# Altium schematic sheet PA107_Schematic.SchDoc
size A3; SheetNumber: 1; SheetTotal: 1
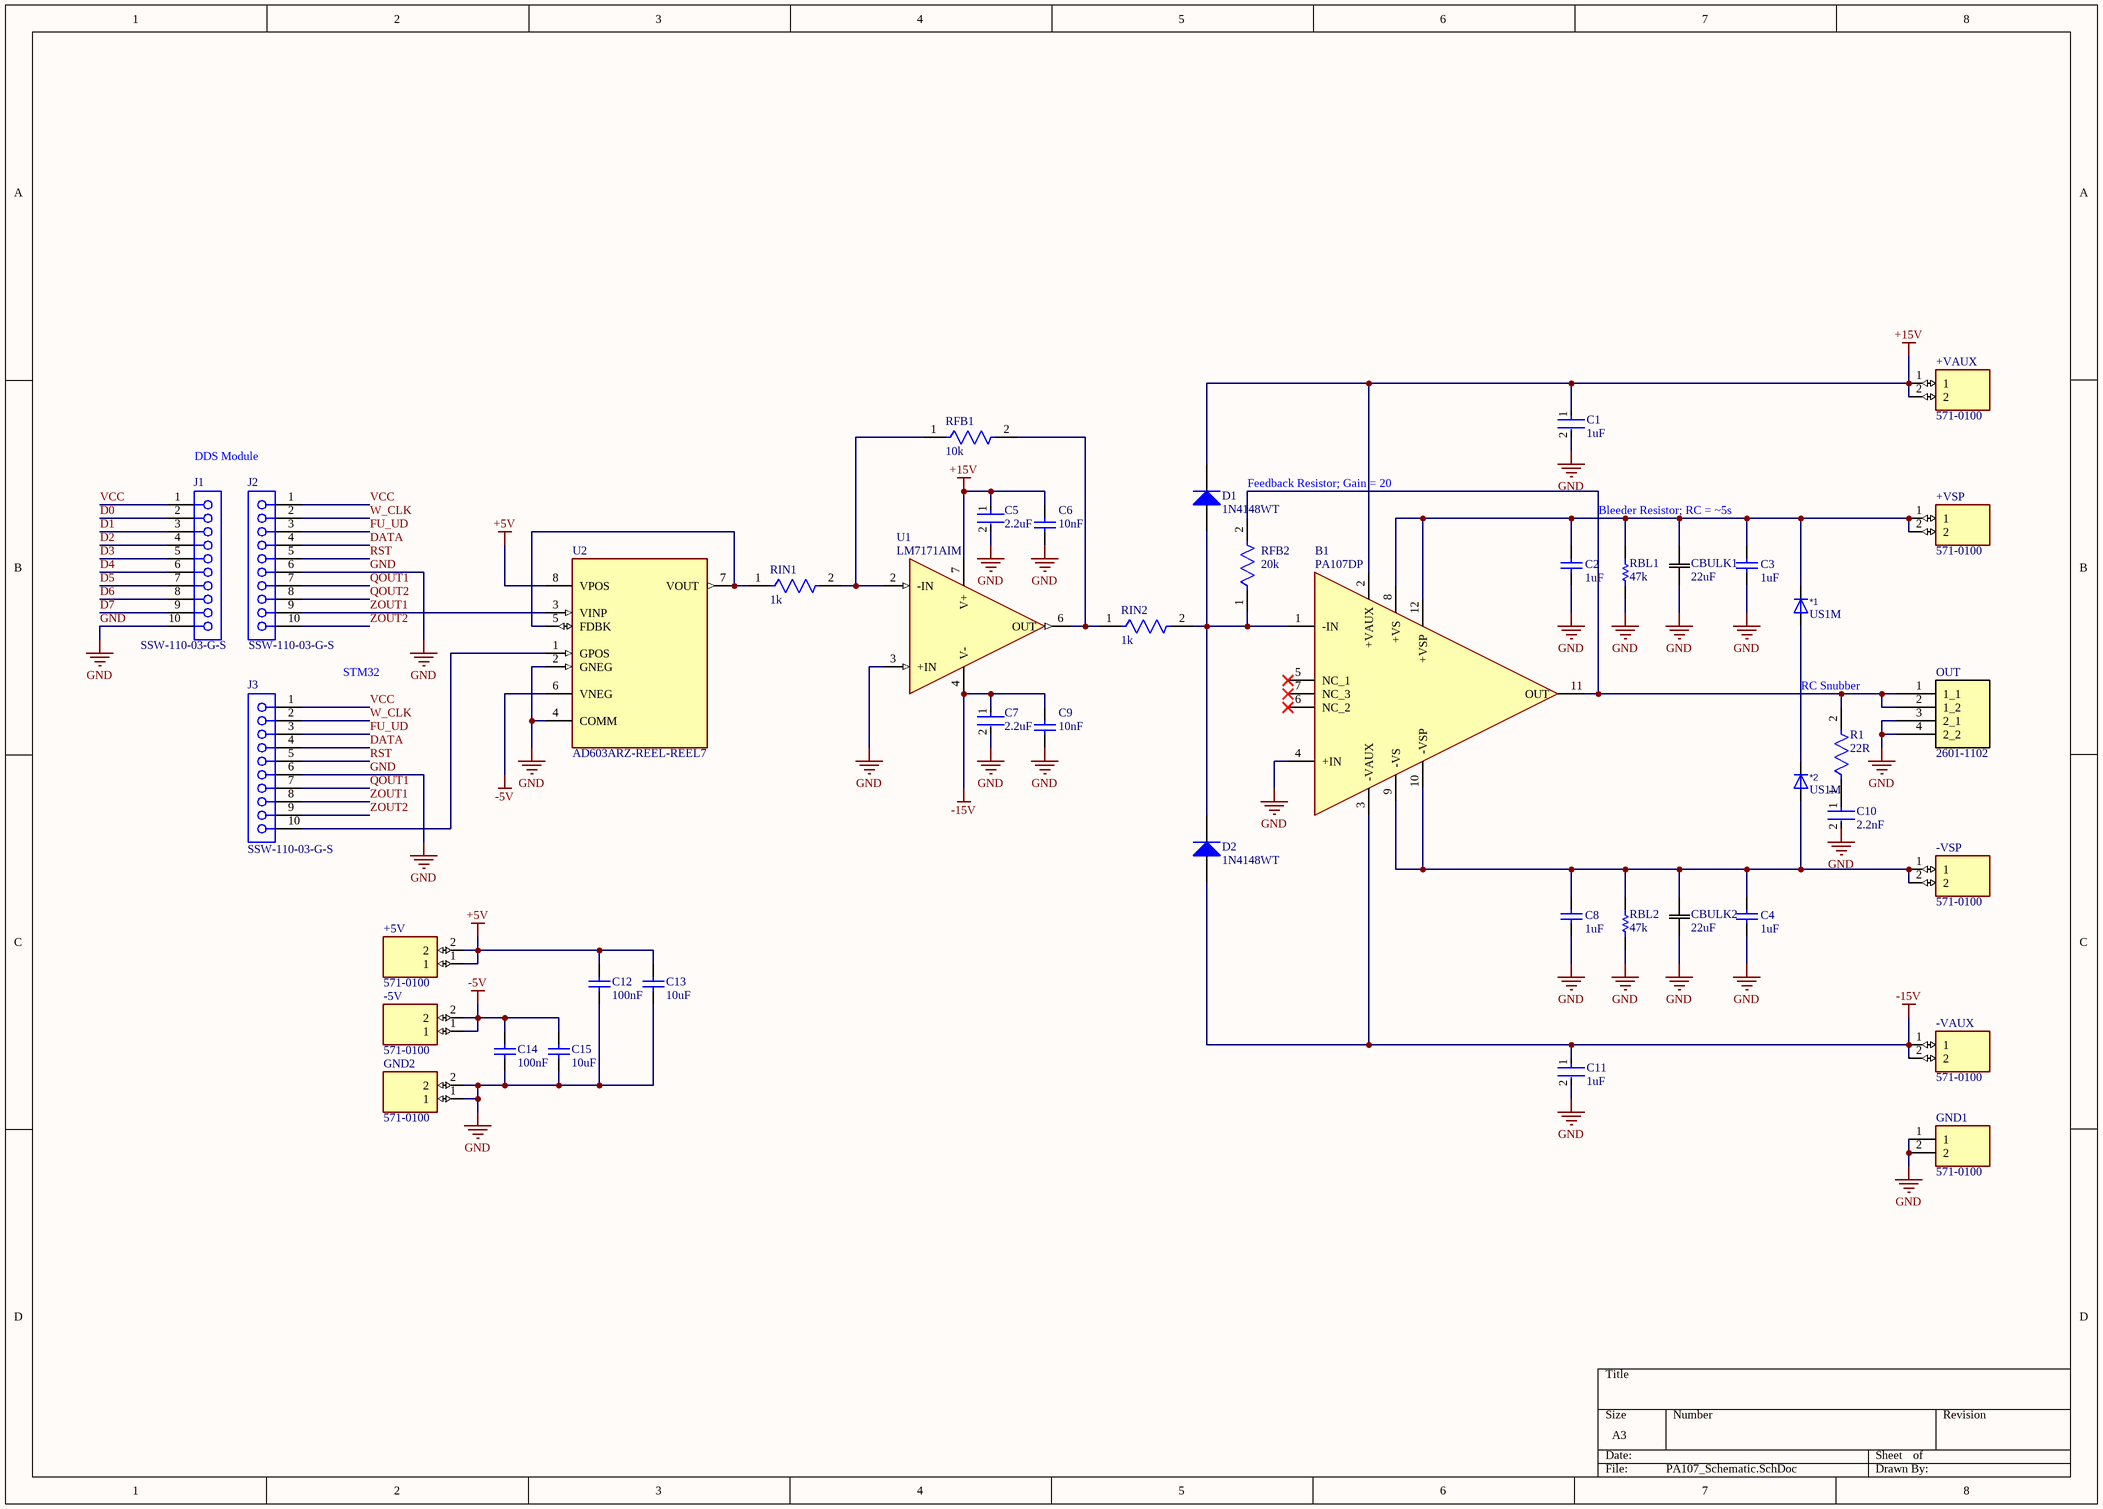
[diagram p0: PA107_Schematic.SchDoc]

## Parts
*1  US1M  [DO-214AC_SMA]
*2  US1M  [DO-214AC_SMA]
+5V  571-0100  [571-0100]
+VAUX  571-0100  [571-0100]
+VSP  571-0100  [571-0100]
-5V  571-0100  [571-0100]
-VAUX  571-0100  [571-0100]
-VSP  571-0100  [571-0100]
B1  PA107DP  [PA107DP]
C1  1uF  [FP-CC0805-0_85-MFG]
C2  1uF  [CAPC4532X279N]
C3  1uF  [CAPC4532X279N]
C4  1uF  [CAPC4532X279N]
C5  2.2uF  [FP-CC0805-0_85-MFG]
C6  10nF  [CAPC2013X145X48LL20T23]
C7  2.2uF  [FP-CC0805-0_85-MFG]
C8  1uF  [CAPC4532X279N]
C9  10nF  [CAPC2013X145X48LL20T23]
C10  2.2nF  [FP-HV1812-IPC_A]
C11  1uF  [FP-CC0805-0_85-MFG]
C12  100nF  [CAPC2013X145X48LL20T23]
C13  10uF  [CAPC2013X140X50ML20T25]
C14  100nF  [CAPC2013X145X48LL20T23]
C15  10uF  [CAPC2013X140X50ML20T25]
CBULK1  22uF  [CAP_BX_10x16_RUB]
CBULK2  22uF  [CAP_BX_10x16_RUB]
D1  1N4148WT  [FAIR-SOD-523F-2_V]
D2  1N4148WT  [FAIR-SOD-523F-2_V]
GND1  571-0100  [5710100]
GND2  571-0100  [571-0100]
J1  SSW-110-03-G-S  [SMTC-SSW-110-03-X-S]
J2  SSW-110-03-G-S  [SMTC-SSW-110-03-X-S]
J3  SSW-110-03-G-S  [SMTC-SSW-110-03-X-S]
OUT  2601-1102  [CONN2_2601-1102_WAG]
R1  22R  [FP-CRGP2512-IPC_C]
RBL1  47k  [RESC1210(3225)_L]
RBL2  47k  [RESC1210(3225)_L]
RFB1  10k  [FP-SR0805-MFG]
RFB2  20k  [FP-CRCW0805-HPe3-IPC_A]
RIN1  1k  [FP-CRCW0805-HPe3-IPC_B]
RIN2  1k  [FP-CRCW0805-HPe3-IPC_B]
U1  LM7171AIM  [SOIC127P599X175-8N]
U2  AD603ARZ-REEL-REEL7  [SOIC127P600X175-8N]

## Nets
+5V: +5V.1 +5V.2 C12.2 C13.2 U2.8(VPOS)
+15V: +VAUX.1 +VAUX.2 B1.2(+VAUX) C1.1 C5.1 C6.2 D1.1(K) U1.7(V+)
-5V: -5V.1 -5V.2 C14.2 C15.2 U2.6(VNEG)
-15V: -VAUX.1 -VAUX.2 B1.3(-VAUX) C7.1 C9.2 C11.1 D2.2(A) U1.4(V-)
GND: B1.4(+IN) C1.2 C2.1 C3.1 C4.1 C5.2 C6.1 C7.2 C8.1 C9.1 C10.2 C11.2 C12.1 C13.1 C14.1 C15.1 CBULK1.1 CBULK2.1 GND1.1 GND1.2 GND2.1 GND2.2 J1.10 J2.6 J3.6 OUT.3(2_1) OUT.4(2_2) RBL1.1 RBL2.1 U1.3(+IN) U2.2(GNEG) U2.4(COMM)
D0: J1.2
D1: J1.3
D2: J1.4
D3: J1.5
D4: J1.6
D5: J1.7
D6: J1.8
D7: J1.9
DATA: J2.4 J3.4
FU_UD: J2.3 J3.3
QOUT1: J2.7 J3.7
QOUT2: J2.8
RST: J2.5 J3.5
VCC: J1.1 J2.1 J3.1
W_CLK: J2.2 J3.2
ZOUT1: J2.9 J3.8 U2.3(VINP)
ZOUT2: J2.10 J3.9
Net*1_1: *1.1(K) +VSP.1 +VSP.2 B1.8(+VS) B1.12(+VSP) C2.2 C3.2 CBULK1.2 RBL1.2
Net*1_2: *1.2(A) *2.1(K)
Net*2_2: *2.2(A) -VSP.1 -VSP.2 B1.9(-VS) B1.10(-VSP) C4.2 C8.2 CBULK2.2 RBL2.2
NetB1_1: B1.1(-IN) D1.2(A) D2.1(K) RFB2.1 RIN2.2
NetB1_11: B1.11(OUT) OUT.1(1_1) OUT.2(1_2) R1.2 RFB2.2
NetC10_1: C10.1 R1.1
NetJ3_10: J3.10 U2.1(GPOS)
NetRFB1_1: RFB1.1 RIN1.2 U1.2(-IN)
NetRFB1_2: RFB1.2 RIN2.1 U1.6(OUT)
NetRIN1_1: RIN1.1 U2.5(FDBK) U2.7(VOUT)

Not connected (* = marked no-connect by the designer): B1 5(NC_1)* 6(NC_2)* 7(NC_3)*

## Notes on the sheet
- DDS Module
- Feedback Resistor; Gain = 20
- Bleeder Resistor; RC = ~5s
- STM32
- (near R1) RC Snubber

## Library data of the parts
*1 *2 = CMP-307-000068-2: Diode 1000 V 1A Surface Mount DO-214AC (SMA); Reference: D
+5V +VAUX +VSP -5V -VAUX -VSP GND2 = CMP-416-000229-1: Connector Receptacle, Female Sockets Board Edge, Through Hole, Right Angle Black I-Trac; MF: Deltron
B1 = CMP-162-000000-3: PA107; Manufacturer_Name: Apex Microtechnology; Geometry.Height: 22.73mm
C1 C11 = CMP-2100-03605-2: CAP CER 1UF 25V X7R 0805; Manufacturer Part Number: CC0805KKX7R8BB105; Manufacturer: Yageo; Material: Ceramic; Tolerance: 0.1
C2-C4 C8 = CMP-292-000450-2: 1 ÂµF Â±10% 200V Ceramic Capacitor X7R 1812 (4532 Metric); MF: AVX; MP: 18122C105KAT2A
C5 C7 = CMP-03422-001390-1: CAP CER 2.2UF 50V X7R 0805; Manufacturer: Yageo; Manufacturer Part Number: CC0805KKX7R9BB225; Tolerance: 0.1; Material: Ceramic
C6 C9 = CMP-2007-03159-1: 10000 pF ±10% 50V Ceramic Capacitor X7R 0805 (2012 Metric); Manufacturer: Vitramon; Part Number: VJ0805Y103KXAMP
C10 = CMP-00030-71705866-1: HV1812Y222KXHATHV Multilayer Ceramic Capacitor, 2200 pF, 3000 V, ± 10%, X7R, 1812 [4532 Metric]; Voltage Rating: 3kV
C12 C14 = CMP-2007-01796-1: Part Number: VJ0805Y104MXAMT; Manufacturer: Vitramon
C13 C15 = CMP-2007-04702-1: Manufacturer: AVX Interconnect / Elco; Part Number: 0805ZC106KAT2A
CBULK1 CBULK2 = CMP-292-000454-1: No Description Available; Manufacturer_Name: Rubycon
D1 D2 = CMP-0881-00001-1: High Conductance Fast Switching Diode, 75 V, -55 to 150 degC, 2-Pin SOD523F, RoHS; Manufacturer: Fairchild Semiconductor; IR (VR: 75 V)=5 uA Max.; VF: 1 V Max.; BVR (IR: 5 uA)=75 V Min.; CO: 4 pF Max.
GND1 = CMP-165-000000-1: Test Sockets SINGLE PCB SOCK BLK; Manufacturer_Name: DELTRON COMPONENTS; Geometry.Height: 12.4mm
J1-J3 = CMP-1023-00394-1: SQ Post Socket, Through-hole, Vertical, -55 to 125 degC, 2.54 mm Pitch, 10-Pin, Female, RoHS; Manufacturer: Samtec; Pitch: 2.54 mm
OUT = CMP-1234-000000-4: Description; Manufacturer_Name: Wago
R1 = CMP-03211-002108-1: CRGP2512 22Ω 2W ±100ppm/°C 1% 500V; Manufacturer Part Number: CRGP2512F22R; Manufacturer: TE; Tolerance: 0.01
RBL1 RBL2 = CMP-1015-00114-1: 47K 0.5W 5% 1210 (3225 Metric)  SMD; Case-EIA: 1210; Case-Metric: 3225; Value: 47000.00 Ohm
RFB1 = CMP-03412-005404-1: RES SMD 0805 1/2W 1% 10K OHM; Manufacturer Part Number: SR0805FR-4710KL; Manufacturer: Yageo; Value: 10KΩ; Power Rating: 0.5W; Voltage Rating: 150V; Description: SR0805 10KΩ 0.5W 1.00%; Tolerance: 0.01; Automotive Grade: Grade 0
RFB2 = CMP-02407-003063-1: RES Thick Film, 20kΩ, 1%, 0.5W, 100ppm/°C, 0805; Power Rating: 500mW; Voltage Rating: 150V; Resistance: 20kR; Max Power Dissipation: 333mW
RIN1 RIN2 = CMP-02407-008945-1: RES Thick Film, 1kΩ, 5%, 0.5W, 200ppm/°C, 0805; Power Rating: 500mW; Voltage Rating: 150V; Max Power Dissipation: 333mW; Resistance: 1kR
U1 = CMP-399-000036-4: Very High Speed, High Output Current, Voltage Feedback Amplifier; MF: Texas Instruments; MP: LM7171AIMX/NOPB
U2 = CMP-399-000037-2: Low Noise, 90 MHz Variable Gain Amplifier; MF: Analog Devices; MP: AD603ARZ-REEL7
